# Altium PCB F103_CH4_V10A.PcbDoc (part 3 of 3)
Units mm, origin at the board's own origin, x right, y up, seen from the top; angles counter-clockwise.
Board outline 100.1 x 70.1 mm, 2 copper layers (TOP, BOTTOM), stack 1.6 mm thick; 116 components, 94 nets, 464 pads, 459 vias.
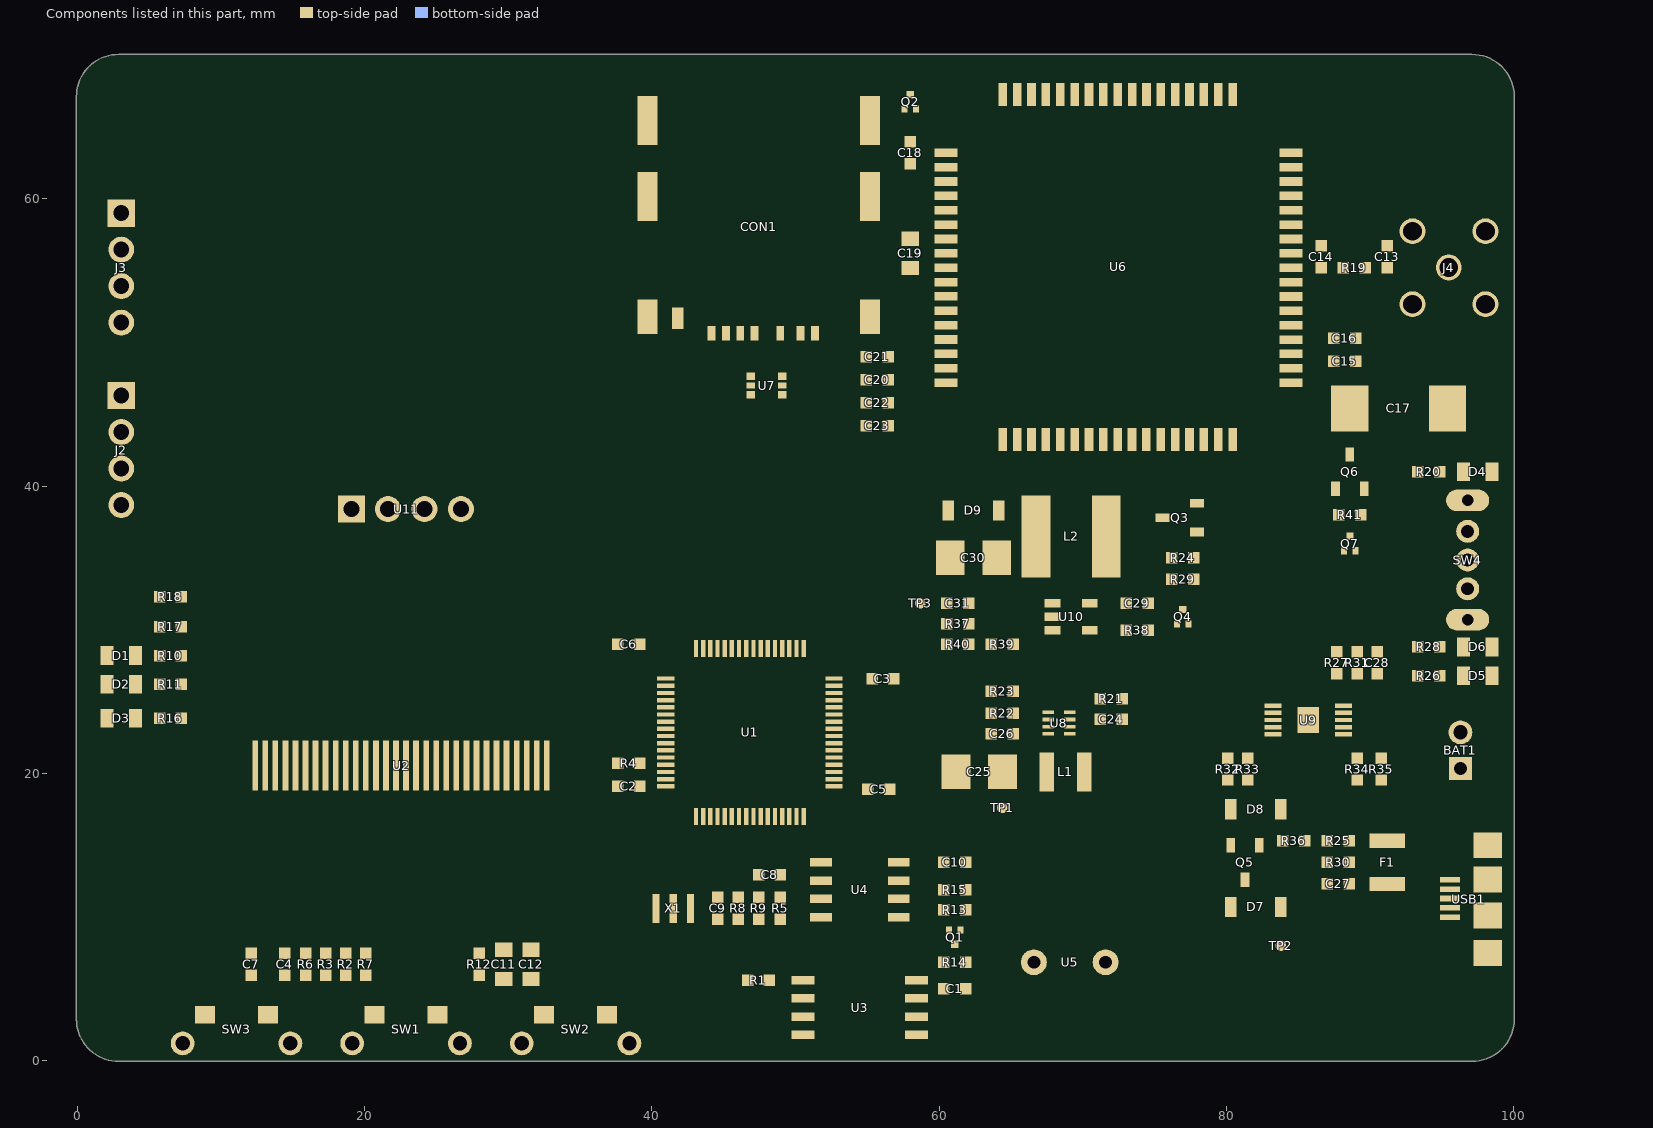
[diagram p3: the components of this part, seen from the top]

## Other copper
TOP:
  pour cut-out: 0,0 0.254,0 0.254,0.254 0,0.254
  pour cut-out: 0,0 0.254,0 0.254,0.254 0,0.254
  pour cut-out: 0,0 0.254,0 0.254,0.254 0,0.254
  pour cut-out: 0,0 0.254,0 0.254,0.254 0,0.254
  pour cut-out: 0,0 0.254,0 0.254,0.254 0,0.254
  pour cut-out: 0,0 0.254,0 0.254,0.254 0,0.254
  pour cut-out: 0,0 0.254,0 0.254,0.254 0,0.254
  pour cut-out: 0,0 0.254,0 0.254,0.254 0,0.254
  pour cut-out: 0,0 0.254,0 0.254,0.254 0,0.254
  pour cut-out: 0,0 0.254,0 0.254,0.254 0,0.254
  pour cut-out: 0,0 0.254,0 0.254,0.254 0,0.254
  pour cut-out: 0,0 0.254,0 0.254,0.254 0,0.254
  pour cut-out: 0,0 0.254,0 0.254,0.254 0,0.254
  pour cut-out: 0,0 0.254,0 0.254,0.254 0,0.254
  pour cut-out: 0,0 0.254,0 0.254,0.254 0,0.254
  pour cut-out: 0,0 0.254,0 0.254,0.254 0,0.254
  pour cut-out: 0,0 0.254,0 0.254,0.254 0,0.254
  pour cut-out: 0,0 0.254,0 0.254,0.254 0,0.254
  pour cut-out: 0,0 0.254,0 0.254,0.254 0,0.254
  pour cut-out: 0,0 0.254,0 0.254,0.254 0,0.254
  pour cut-out: 0,0 0.254,0 0.254,0.254 0,0.254
  pour cut-out: 0,0 0.254,0 0.254,0.254 0,0.254
  pour cut-out: 0,0 0.254,0 0.254,0.254 0,0.254
  pour cut-out: 0,0 0.254,0 0.254,0.254 0,0.254
  pour cut-out: 0,0 0.254,0 0.254,0.254 0,0.254
  pour cut-out: 0,0 0.254,0 0.254,0.254 0,0.254
  pour cut-out: 0,0 0.254,0 0.254,0.254 0,0.254
  pour cut-out: 0,0 0.254,0 0.254,0.254 0,0.254
  pour cut-out: 0,0 0.254,0 0.254,0.254 0,0.254
  pour cut-out: 0,0 0.254,0 0.254,0.254 0,0.254
  pour cut-out: 0,0 0.254,0 0.254,0.254 0,0.254
  pour cut-out: 0,0 0.254,0 0.254,0.254 0,0.254
  pour cut-out: 0,0 0.254,0 0.254,0.254 0,0.254
  pour cut-out: 0,0 0.254,0 0.254,0.254 0,0.254
  pour cut-out: 0,0 0.254,0 0.254,0.254 0,0.254
  pour cut-out: 0,0 0.254,0 0.254,0.254 0,0.254
  pour cut-out: 0,0 0.254,0 0.254,0.254 0,0.254
  pour cut-out: 0,0 0.254,0 0.254,0.254 0,0.254
  pour cut-out: 0,0 0.254,0 0.254,0.254 0,0.254
  pour cut-out: 0,0 0.254,0 0.254,0.254 0,0.254
  pour cut-out: 0,0 0.254,0 0.254,0.254 0,0.254
  pour cut-out: 0,0 0.254,0 0.254,0.254 0,0.254
  pour cut-out: 0,0 0.254,0 0.254,0.254 0,0.254
  pour cut-out: 0,0 0.254,0 0.254,0.254 0,0.254
  pour cut-out: 0,0 0.254,0 0.254,0.254 0,0.254
  pour cut-out: 0,0 0.254,0 0.254,0.254 0,0.254
  pour cut-out: 0,0 0.254,0 0.254,0.254 0,0.254
  pour cut-out: 0,0 0.254,0 0.254,0.254 0,0.254
  pour cut-out: 0,0 0.254,0 0.254,0.254 0,0.254
  pour cut-out: 0,0 0.254,0 0.254,0.254 0,0.254
  pour cut-out: 0,0 0.254,0 0.254,0.254 0,0.254
  pour cut-out: 0,0 0.254,0 0.254,0.254 0,0.254
  pour cut-out: 0,0 0.254,0 0.254,0.254 0,0.254
  pour cut-out: 0,0 0.254,0 0.254,0.254 0,0.254
  pour cut-out: 0,0 0.254,0 0.254,0.254 0,0.254
  pour cut-out: 0,0 0.254,0 0.254,0.254 0,0.254
  pour cut-out: 0,0 0.254,0 0.254,0.254 0,0.254
  pour cut-out: 0,0 0.254,0 0.254,0.254 0,0.254
  pour cut-out: 0,0 0.254,0 0.254,0.254 0,0.254
  pour cut-out: 0,0 0.254,0 0.254,0.254 0,0.254
  pour cut-out: 0,0 0.254,0 0.254,0.254 0,0.254
  pour cut-out: 0,0 0.254,0 0.254,0.254 0,0.254
  pour cut-out: 0,0 0.254,0 0.254,0.254 0,0.254
  pour cut-out: 0,0 0.254,0 0.254,0.254 0,0.254
  pour cut-out: 0,0 0.254,0 0.254,0.254 0,0.254
  pour cut-out: 0,0 0.254,0 0.254,0.254 0,0.254
  pour cut-out: 0,0 0.254,0 0.254,0.254 0,0.254
  pour cut-out: 0,0 0.254,0 0.254,0.254 0,0.254
  pour cut-out: 0,0 0.254,0 0.254,0.254 0,0.254
  pour cut-out: 0,0 0.254,0 0.254,0.254 0,0.254
  pour cut-out: 0,0 0.254,0 0.254,0.254 0,0.254
  pour cut-out: 0,0 0.254,0 0.254,0.254 0,0.254
  pour cut-out: 0,0 0.254,0 0.254,0.254 0,0.254
  pour cut-out: 0,0 0.254,0 0.254,0.254 0,0.254
  pour cut-out: 0,0 0.254,0 0.254,0.254 0,0.254
  pour cut-out: 0,0 0.254,0 0.254,0.254 0,0.254
  pour cut-out: 0,0 0.254,0 0.254,0.254 0,0.254
  pour cut-out: 0,0 0.254,0 0.254,0.254 0,0.254
  pour cut-out: 0,0 0.254,0 0.254,0.254 0,0.254
  pour cut-out: 0,0 0.254,0 0.254,0.254 0,0.254
  pour cut-out: 0,0 0.254,0 0.254,0.254 0,0.254
  pour cut-out: 99.409,57.74 99.362,58.094 99.226,58.425 99.008,58.708 98.725,58.926 98.394,59.062 98.04,59.109 97.686,59.062 97.355,58.926 97.072,58.708 96.854,58.425 96.718,58.094 96.671,57.74 96.718,57.386 96.854,57.055 97.072,56.772 97.355,56.554 97.686,56.418 98.04,56.371 98.394,56.418 98.725,56.554 99.008,56.772 99.226,57.055 99.362,57.386 99.409,57.74
  pour cut-out: 99.409,52.66 99.362,53.014 99.226,53.345 99.008,53.628 98.725,53.846 98.394,53.982 98.04,54.029 97.686,53.982 97.355,53.846 97.072,53.628 96.854,53.345 96.718,53.014 96.671,52.66 96.718,52.306 96.854,51.975 97.072,51.692 97.355,51.474 97.686,51.338 98.04,51.291 98.394,51.338 98.725,51.474 99.008,51.692 99.226,51.975 99.362,52.306 99.409,52.66
  pour cut-out: 94.329,57.74 94.282,58.094 94.146,58.425 93.928,58.708 93.645,58.926 93.314,59.062 92.96,59.109 92.606,59.062 92.275,58.926 91.992,58.708 91.774,58.425 91.638,58.094 91.591,57.74 91.638,57.386 91.774,57.055 91.992,56.772 92.275,56.554 92.606,56.418 92.96,56.371 93.314,56.418 93.645,56.554 93.928,56.772 94.146,57.055 94.282,57.386 94.329,57.74
  pour cut-out: 94.329,52.66 94.282,53.014 94.146,53.345 93.928,53.628 93.645,53.846 93.314,53.982 92.96,54.029 92.606,53.982 92.275,53.846 91.992,53.628 91.774,53.345 91.638,53.014 91.591,52.66 91.638,52.306 91.774,51.975 91.992,51.692 92.275,51.474 92.606,51.338 92.96,51.291 93.314,51.338 93.645,51.474 93.928,51.692 94.146,51.975 94.282,52.306 94.329,52.66
  pour cut-out: 82.255,48.2 82.222,48.535 82.125,48.857 81.966,49.154 81.752,49.414 81.492,49.628 81.195,49.787 80.873,49.884 80.538,49.917 80.203,49.884 79.881,49.787 79.584,49.628 79.324,49.414 79.11,49.154 78.951,48.857 78.854,48.535 78.821,48.2 78.854,47.865 78.951,47.543 79.11,47.246 79.324,46.986 79.584,46.772 79.881,46.613 80.203,46.516 80.538,46.483 80.873,46.516 81.195,46.613 81.492,46.772 81.752,46.986 81.966,47.246 82.125,47.543 82.222,47.865 82.255,48.2
  pour cut-out: 32.912,66.6 32.864,67.09 32.721,67.561 32.489,67.996 32.176,68.376 31.796,68.689 31.361,68.921 30.89,69.064 30.4,69.112 29.91,69.064 29.439,68.921 29.004,68.689 28.624,68.376 28.311,67.996 28.079,67.561 27.936,67.09 27.888,66.6 27.936,66.11 28.079,65.639 28.311,65.204 28.624,64.824 29.004,64.511 29.439,64.279 29.91,64.136 30.4,64.088 30.89,64.136 31.361,64.279 31.796,64.511 32.176,64.824 32.489,65.204 32.721,65.639 32.864,66.11 32.912,66.6
  pour cut-out: 17.912,66.6 17.864,67.09 17.721,67.561 17.489,67.996 17.176,68.376 16.796,68.689 16.361,68.921 15.89,69.064 15.4,69.112 14.91,69.064 14.439,68.921 14.004,68.689 13.624,68.376 13.311,67.996 13.079,67.561 12.936,67.09 12.888,66.6 12.936,66.11 13.079,65.639 13.311,65.204 13.624,64.824 14.004,64.511 14.439,64.279 14.91,64.136 15.4,64.088 15.89,64.136 16.361,64.279 16.796,64.511 17.176,64.824 17.489,65.204 17.721,65.639 17.864,66.11 17.912,66.6
  pour cut-out: 0,0 0.254,0 0.254,0.254 0,0.254
  pour cut-out: 0,0 0.254,0 0.254,0.254 0,0.254
  pour cut-out: 0,0 0.254,0 0.254,0.254 0,0.254
  pour cut-out: 0,0 0.254,0 0.254,0.254 0,0.254
  pour cut-out: 0,0 0.254,0 0.254,0.254 0,0.254
  pour cut-out: 0,0 0.254,0 0.254,0.254 0,0.254
  pour cut-out: 0,0 0.254,0 0.254,0.254 0,0.254
  pour cut-out: 0,0 0.254,0 0.254,0.254 0,0.254
  pour cut-out: 0,0 0.254,0 0.254,0.254 0,0.254
  pour cut-out: 0,0 0.254,0 0.254,0.254 0,0.254
  pour cut-out: 0,0 0.254,0 0.254,0.254 0,0.254
  pour cut-out: 0,0 0.254,0 0.254,0.254 0,0.254
  pour cut-out: 0,0 0.254,0 0.254,0.254 0,0.254
  pour cut-out: 0,0 0.254,0 0.254,0.254 0,0.254
  pour cut-out: 0,0 0.254,0 0.254,0.254 0,0.254
  pour cut-out: 0,0 0.254,0 0.254,0.254 0,0.254
  pour cut-out: 0,0 0.254,0 0.254,0.254 0,0.254
  pour cut-out: 0,0 0.254,0 0.254,0.254 0,0.254
  pour cut-out: 0,0 0.254,0 0.254,0.254 0,0.254
  pour cut-out: 0,0 0.254,0 0.254,0.254 0,0.254
  pour cut-out: 0,0 0.254,0 0.254,0.254 0,0.254
  pour cut-out: 0,0 0.254,0 0.254,0.254 0,0.254
  pour cut-out: 0,0 0.254,0 0.254,0.254 0,0.254
  pour cut-out: 0,0 0.254,0 0.254,0.254 0,0.254
  pour cut-out: 0,0 0.254,0 0.254,0.254 0,0.254
  pour cut-out: 0,0 0.254,0 0.254,0.254 0,0.254
  pour cut-out: 0,0 0.254,0 0.254,0.254 0,0.254
  pour cut-out: 0,0 0.254,0 0.254,0.254 0,0.254
  pour cut-out: 0,0 0.254,0 0.254,0.254 0,0.254
  pour cut-out: 0,0 0.254,0 0.254,0.254 0,0.254
  pour cut-out: 0,0 0.254,0 0.254,0.254 0,0.254
  pour cut-out: 0,0 0.254,0 0.254,0.254 0,0.254
  pour cut-out: 0,0 0.254,0 0.254,0.254 0,0.254
  pour cut-out: 0,0 0.254,0 0.254,0.254 0,0.254
  pour cut-out: 0,0 0.254,0 0.254,0.254 0,0.254
  pour cut-out: 0,0 0.254,0 0.254,0.254 0,0.254
  pour cut-out: 0,0 0.254,0 0.254,0.254 0,0.254
  pour cut-out: 0,0 0.254,0 0.254,0.254 0,0.254
  pour cut-out: 0,0 0.254,0 0.254,0.254 0,0.254
  pour cut-out: 0,0 0.254,0 0.254,0.254 0,0.254
  pour cut-out: 0,0 0.254,0 0.254,0.254 0,0.254
  pour cut-out: 0,0 0.254,0 0.254,0.254 0,0.254
  pour cut-out: 0,0 0.254,0 0.254,0.254 0,0.254
  pour cut-out: 0,0 0.254,0 0.254,0.254 0,0.254
  pour cut-out: 0,0 0.254,0 0.254,0.254 0,0.254
  pour cut-out: 0,0 0.254,0 0.254,0.254 0,0.254
  pour cut-out: 0,0 0.254,0 0.254,0.254 0,0.254
  pour cut-out: 0,0 0.254,0 0.254,0.254 0,0.254
  pour cut-out: 0,0 0.254,0 0.254,0.254 0,0.254
  pour cut-out: 0,0 0.254,0 0.254,0.254 0,0.254
  pour cut-out: 0,0 0.254,0 0.254,0.254 0,0.254
  pour cut-out: 0,0 0.254,0 0.254,0.254 0,0.254
  pour cut-out: 0,0 0.254,0 0.254,0.254 0,0.254
  pour cut-out: 0,0 0.254,0 0.254,0.254 0,0.254
  pour cut-out: 0,0 0.254,0 0.254,0.254 0,0.254
  pour cut-out: 0,0 0.254,0 0.254,0.254 0,0.254
  pour cut-out: 0,0 0.254,0 0.254,0.254 0,0.254
  pour cut-out: 0,0 0.254,0 0.254,0.254 0,0.254
  pour cut-out: 0,0 0.254,0 0.254,0.254 0,0.254
  pour cut-out: 0,0 0.254,0 0.254,0.254 0,0.254
  pour cut-out: 0,0 0.254,0 0.254,0.254 0,0.254
  pour cut-out: 0,0 0.254,0 0.254,0.254 0,0.254
  pour cut-out: 0,0 0.254,0 0.254,0.254 0,0.254
  pour cut-out: 0,0 0.254,0 0.254,0.254 0,0.254
  pour cut-out: 0,0 0.254,0 0.254,0.254 0,0.254
  pour cut-out: 0,0 0.254,0 0.254,0.254 0,0.254
  pour cut-out: 0,0 0.254,0 0.254,0.254 0,0.254
  pour cut-out: 0,0 0.254,0 0.254,0.254 0,0.254
  pour cut-out: 0,0 0.254,0 0.254,0.254 0,0.254
  pour cut-out: 0,0 0.254,0 0.254,0.254 0,0.254
  pour cut-out: 0,0 0.254,0 0.254,0.254 0,0.254
  pour cut-out: 0,0 0.254,0 0.254,0.254 0,0.254
  pour cut-out: 0,0 0.254,0 0.254,0.254 0,0.254
  pour cut-out: 0,0 0.254,0 0.254,0.254 0,0.254
  pour cut-out: 0,0 0.254,0 0.254,0.254 0,0.254
  pour cut-out: 0,0 0.254,0 0.254,0.254 0,0.254
  pour cut-out: 0,0 0.254,0 0.254,0.254 0,0.254
  pour cut-out: 0,0 0.254,0 0.254,0.254 0,0.254
  pour cut-out: 0,0 0.254,0 0.254,0.254 0,0.254
  pour cut-out: 0,0 0.254,0 0.254,0.254 0,0.254
  pour cut-out: 0,0 0.254,0 0.254,0.254 0,0.254
  pour cut-out: 0,0 0.254,0 0.254,0.254 0,0.254
  pour cut-out: 0,0 0.254,0 0.254,0.254 0,0.254
  pour cut-out: 0,0 0.254,0 0.254,0.254 0,0.254
  pour cut-out: 0,0 0.254,0 0.254,0.254 0,0.254
  pour cut-out: 0,0 0.254,0 0.254,0.254 0,0.254
  pour cut-out: 0,0 0.254,0 0.254,0.254 0,0.254
  pour cut-out: 0,0 0.254,0 0.254,0.254 0,0.254
  pour cut-out: 36.462,1.5 36.415,1.734 36.283,1.933 36.084,2.065 35.85,2.112 35.616,2.065 35.417,1.933 35.285,1.734 35.238,1.5 35.285,1.266 35.417,1.067 35.616,0.935 35.85,0.888 36.084,0.935 36.283,1.067 36.415,1.266 36.462,1.5
  pour cut-out: 96.423,13.3 96.398,13.423 96.328,13.528 96.223,13.598 96.1,13.623 95.977,13.598 95.872,13.528 95.802,13.423 95.777,13.3 95.802,13.177 95.872,13.072 95.977,13.002 96.1,12.977 96.223,13.002 96.328,13.072 96.398,13.177 96.423,13.3
  pour cut-out: 0,0 0.254,0 0.254,0.254 0,0.254
  pour cut-out: 0,0 0.254,0 0.254,0.254 0,0.254
  pour cut-out: 0,0 0.254,0 0.254,0.254 0,0.254
  pour cut-out: 0,0 0.254,0 0.254,0.254 0,0.254
  pour cut-out: 12.862,1.5 12.815,1.734 12.683,1.933 12.484,2.065 12.25,2.112 12.016,2.065 11.817,1.933 11.685,1.734 11.638,1.5 11.685,1.266 11.817,1.067 12.016,0.935 12.25,0.888 12.484,0.935 12.683,1.067 12.815,1.266 12.862,1.5
  pour cut-out: 0,0 0.254,0 0.254,0.254 0,0.254
  pour cut-out: 0,0 0.254,0 0.254,0.254 0,0.254
  pour cut-out: 0,0 0.254,0 0.254,0.254 0,0.254
  pour cut-out: 0,0 0.254,0 0.254,0.254 0,0.254
  pour cut-out: 0,0 0.254,0 0.254,0.254 0,0.254
  pour cut-out: 0,0 0.254,0 0.254,0.254 0,0.254
  pour cut-out: 0,0 0.254,0 0.254,0.254 0,0.254
  pour cut-out: 0,0 0.254,0 0.254,0.254 0,0.254
  pour cut-out: 0,0 0.254,0 0.254,0.254 0,0.254
  pour cut-out: 0,0 0.254,0 0.254,0.254 0,0.254
  pour cut-out: 0,0 0.254,0 0.254,0.254 0,0.254
BOTTOM:
  pour cut-out: 24.662,1.5 24.615,1.734 24.483,1.933 24.284,2.065 24.05,2.112 23.816,2.065 23.617,1.933 23.485,1.734 23.438,1.5 23.485,1.266 23.617,1.067 23.816,0.935 24.05,0.888 24.284,0.935 24.483,1.067 24.615,1.266 24.662,1.5
  pour cut-out: 22.362,1.5 22.315,1.734 22.183,1.933 21.984,2.065 21.75,2.112 21.516,2.065 21.317,1.933 21.185,1.734 21.138,1.5 21.185,1.266 21.317,1.067 21.516,0.935 21.75,0.888 21.984,0.935 22.183,1.067 22.315,1.266 22.362,1.5
  pour cut-out: 99.409,57.74 99.362,58.094 99.226,58.425 99.008,58.708 98.725,58.926 98.394,59.062 98.04,59.109 97.686,59.062 97.355,58.926 97.072,58.708 96.854,58.425 96.718,58.094 96.671,57.74 96.718,57.386 96.854,57.055 97.072,56.772 97.355,56.554 97.686,56.418 98.04,56.371 98.394,56.418 98.725,56.554 99.008,56.772 99.226,57.055 99.362,57.386 99.409,57.74
  pour cut-out: 99.409,52.66 99.362,53.014 99.226,53.345 99.008,53.628 98.725,53.846 98.394,53.982 98.04,54.029 97.686,53.982 97.355,53.846 97.072,53.628 96.854,53.345 96.718,53.014 96.671,52.66 96.718,52.306 96.854,51.975 97.072,51.692 97.355,51.474 97.686,51.338 98.04,51.291 98.394,51.338 98.725,51.474 99.008,51.692 99.226,51.975 99.362,52.306 99.409,52.66
  pour cut-out: 96.904,55.216 96.856,55.584 96.714,55.926 96.488,56.22 96.194,56.446 95.852,56.588 95.484,56.636 95.116,56.588 94.774,56.446 94.48,56.22 94.254,55.926 94.112,55.584 94.064,55.216 94.112,54.848 94.254,54.506 94.48,54.212 94.774,53.986 95.116,53.844 95.484,53.796 95.852,53.844 96.194,53.986 96.488,54.212 96.714,54.506 96.856,54.848 96.904,55.216
  pour cut-out: 94.329,57.74 94.282,58.094 94.146,58.425 93.928,58.708 93.645,58.926 93.314,59.062 92.96,59.109 92.606,59.062 92.275,58.926 91.992,58.708 91.774,58.425 91.638,58.094 91.591,57.74 91.638,57.386 91.774,57.055 91.992,56.772 92.275,56.554 92.606,56.418 92.96,56.371 93.314,56.418 93.645,56.554 93.928,56.772 94.146,57.055 94.282,57.386 94.329,57.74
  pour cut-out: 94.329,52.66 94.282,53.014 94.146,53.345 93.928,53.628 93.645,53.846 93.314,53.982 92.96,54.029 92.606,53.982 92.275,53.846 91.992,53.628 91.774,53.345 91.638,53.014 91.591,52.66 91.638,52.306 91.774,51.975 91.992,51.692 92.275,51.474 92.606,51.338 92.96,51.291 93.314,51.338 93.645,51.474 93.928,51.692 94.146,51.975 94.282,52.306 94.329,52.66
  pour cut-out: 73.02,6.85 72.972,7.218 72.83,7.56 72.604,7.854 72.31,8.08 71.968,8.222 71.6,8.27 71.232,8.222 70.89,8.08 70.596,7.854 70.37,7.56 70.228,7.218 70.18,6.85 70.228,6.482 70.37,6.14 70.596,5.846 70.89,5.62 71.232,5.478 71.6,5.43 71.968,5.478 72.31,5.62 72.604,5.846 72.83,6.14 72.972,6.482 73.02,6.85
  pour cut-out: 68.02,6.85 67.972,7.218 67.83,7.56 67.604,7.854 67.31,8.08 66.968,8.222 66.6,8.27 66.232,8.222 65.89,8.08 65.596,7.854 65.37,7.56 65.228,7.218 65.18,6.85 65.228,6.482 65.37,6.14 65.596,5.846 65.89,5.62 66.232,5.478 66.6,5.43 66.968,5.478 67.31,5.62 67.604,5.846 67.83,6.14 67.972,6.482 68.02,6.85
  pour cut-out: 96.423,13.3 96.398,13.423 96.328,13.528 96.223,13.598 96.1,13.623 95.977,13.598 95.872,13.528 95.802,13.423 95.777,13.3 95.802,13.177 95.872,13.072 95.977,13.002 96.1,12.977 96.223,13.002 96.328,13.072 96.398,13.177 96.423,13.3
  pour cut-out: 96.423,9.3 96.398,9.423 96.328,9.528 96.223,9.598 96.1,9.623 95.977,9.598 95.872,9.528 95.802,9.423 95.777,9.3 95.802,9.177 95.872,9.072 95.977,9.002 96.1,8.977 96.223,9.002 96.328,9.072 96.398,9.177 96.423,9.3
  pour cut-out: 82.255,48.2 82.222,48.535 82.125,48.857 81.966,49.154 81.752,49.414 81.492,49.628 81.195,49.787 80.873,49.884 80.538,49.917 80.203,49.884 79.881,49.787 79.584,49.628 79.324,49.414 79.11,49.154 78.951,48.857 78.854,48.535 78.821,48.2 78.854,47.865 78.951,47.543 79.11,47.246 79.324,46.986 79.584,46.772 79.881,46.613 80.203,46.516 80.538,46.483 80.873,46.516 81.195,46.613 81.492,46.772 81.752,46.986 81.966,47.246 82.125,47.543 82.222,47.865 82.255,48.2
  pour cut-out: 36.462,1.5 36.415,1.734 36.283,1.933 36.084,2.065 35.85,2.112 35.616,2.065 35.417,1.933 35.285,1.734 35.238,1.5 35.285,1.266 35.417,1.067 35.616,0.935 35.85,0.888 36.084,0.935 36.283,1.067 36.415,1.266 36.462,1.5
  pour cut-out: 34.162,1.5 34.115,1.734 33.983,1.933 33.784,2.065 33.55,2.112 33.316,2.065 33.117,1.933 32.985,1.734 32.938,1.5 32.985,1.266 33.117,1.067 33.316,0.935 33.55,0.888 33.784,0.935 33.983,1.067 34.115,1.266 34.162,1.5
  pour cut-out: 32.912,66.6 32.864,67.09 32.721,67.561 32.489,67.996 32.176,68.376 31.796,68.689 31.361,68.921 30.89,69.064 30.4,69.112 29.91,69.064 29.439,68.921 29.004,68.689 28.624,68.376 28.311,67.996 28.079,67.561 27.936,67.09 27.888,66.6 27.936,66.11 28.079,65.639 28.311,65.204 28.624,64.824 29.004,64.511 29.439,64.279 29.91,64.136 30.4,64.088 30.89,64.136 31.361,64.279 31.796,64.511 32.176,64.824 32.489,65.204 32.721,65.639 32.864,66.11 32.912,66.6
  pour cut-out: 17.912,66.6 17.864,67.09 17.721,67.561 17.489,67.996 17.176,68.376 16.796,68.689 16.361,68.921 15.89,69.064 15.4,69.112 14.91,69.064 14.439,68.921 14.004,68.689 13.624,68.376 13.311,67.996 13.079,67.561 12.936,67.09 12.888,66.6 12.936,66.11 13.079,65.639 13.311,65.204 13.624,64.824 14.004,64.511 14.439,64.279 14.91,64.136 15.4,64.088 15.89,64.136 16.361,64.279 16.796,64.511 17.176,64.824 17.489,65.204 17.721,65.639 17.864,66.11 17.912,66.6
  pour cut-out: 12.862,1.5 12.815,1.734 12.683,1.933 12.484,2.065 12.25,2.112 12.016,2.065 11.817,1.933 11.685,1.734 11.638,1.5 11.685,1.266 11.817,1.067 12.016,0.935 12.25,0.888 12.484,0.935 12.683,1.067 12.815,1.266 12.862,1.5
  pour cut-out: 10.562,1.5 10.515,1.734 10.383,1.933 10.184,2.065 9.95,2.112 9.716,2.065 9.517,1.933 9.385,1.734 9.338,1.5 9.385,1.266 9.517,1.067 9.716,0.935 9.95,0.888 10.184,0.935 10.383,1.067 10.515,1.266 10.562,1.5
  pour cut-out: 0,0 0.254,0 0.254,0.254 0,0.254
  pour cut-out: 0,0 0.254,0 0.254,0.254 0,0.254
  pour cut-out: 0,0 0.254,0 0.254,0.254 0,0.254
  pour cut-out: 0,0 0.254,0 0.254,0.254 0,0.254
  pour cut-out: 0,0 0.254,0 0.254,0.254 0,0.254
  pour cut-out: 0,0 0.254,0 0.254,0.254 0,0.254
  pour cut-out: 0,0 0.254,0 0.254,0.254 0,0.254
  pour cut-out: 0,0 0.254,0 0.254,0.254 0,0.254
  pour cut-out: 0,0 0.254,0 0.254,0.254 0,0.254
  pour cut-out: 0,0 0.254,0 0.254,0.254 0,0.254
  pour cut-out: 0,0 0.254,0 0.254,0.254 0,0.254
  pour cut-out: 0,0 0.254,0 0.254,0.254 0,0.254
  pour cut-out: 0,0 0.254,0 0.254,0.254 0,0.254
  pour cut-out: 0,0 0.254,0 0.254,0.254 0,0.254
  pour cut-out: 0,0 0.254,0 0.254,0.254 0,0.254
  pour cut-out: 0,0 0.254,0 0.254,0.254 0,0.254
  pour cut-out: 0,0 0.254,0 0.254,0.254 0,0.254
  pour cut-out: 0,0 0.254,0 0.254,0.254 0,0.254
  pour cut-out: 0,0 0.254,0 0.254,0.254 0,0.254
  pour cut-out: 0,0 0.254,0 0.254,0.254 0,0.254
  pour cut-out: 0,0 0.254,0 0.254,0.254 0,0.254
  pour cut-out: 0,0 0.254,0 0.254,0.254 0,0.254
  pour cut-out: 0,0 0.254,0 0.254,0.254 0,0.254
  pour cut-out: 0,0 0.254,0 0.254,0.254 0,0.254
  pour cut-out: 0,0 0.254,0 0.254,0.254 0,0.254
  pour cut-out: 0,0 0.254,0 0.254,0.254 0,0.254
  pour cut-out: 0,0 0.254,0 0.254,0.254 0,0.254
  pour cut-out: 0,0 0.254,0 0.254,0.254 0,0.254
  pour cut-out: 0,0 0.254,0 0.254,0.254 0,0.254
  pour cut-out: 0,0 0.254,0 0.254,0.254 0,0.254
  pour cut-out: 0,0 0.254,0 0.254,0.254 0,0.254
  pour cut-out: 0,0 0.254,0 0.254,0.254 0,0.254
  pour cut-out: 0,0 0.254,0 0.254,0.254 0,0.254
  pour cut-out: 0,0 0.254,0 0.254,0.254 0,0.254
  pour cut-out: 0,0 0.254,0 0.254,0.254 0,0.254
  pour cut-out: 0,0 0.254,0 0.254,0.254 0,0.254
  pour cut-out: 0,0 0.254,0 0.254,0.254 0,0.254
  pour cut-out: 0,0 0.254,0 0.254,0.254 0,0.254
  pour cut-out: 0,0 0.254,0 0.254,0.254 0,0.254
  pour cut-out: 0,0 0.254,0 0.254,0.254 0,0.254
  pour cut-out: 0,0 0.254,0 0.254,0.254 0,0.254
  pour cut-out: 0,0 0.254,0 0.254,0.254 0,0.254
  pour cut-out: 0,0 0.254,0 0.254,0.254 0,0.254
  pour cut-out: 0,0 0.254,0 0.254,0.254 0,0.254
  pour cut-out: 0,0 0.254,0 0.254,0.254 0,0.254
  pour cut-out: 0,0 0.254,0 0.254,0.254 0,0.254
  pour cut-out: 0,0 0.254,0 0.254,0.254 0,0.254
  pour cut-out: 0,0 0.254,0 0.254,0.254 0,0.254
  pour cut-out: 0,0 0.254,0 0.254,0.254 0,0.254
  pour cut-out: 0,0 0.254,0 0.254,0.254 0,0.254
  pour cut-out: 0,0 0.254,0 0.254,0.254 0,0.254
  pour cut-out: 0,0 0.254,0 0.254,0.254 0,0.254
  pour cut-out: 0,0 0.254,0 0.254,0.254 0,0.254
  pour cut-out: 0,0 0.254,0 0.254,0.254 0,0.254
  pour cut-out: 0,0 0.254,0 0.254,0.254 0,0.254
  pour cut-out: 0,0 0.254,0 0.254,0.254 0,0.254
  pour cut-out: 0,0 0.254,0 0.254,0.254 0,0.254
  pour cut-out: 0,0 0.254,0 0.254,0.254 0,0.254
  pour cut-out: 0,0 0.254,0 0.254,0.254 0,0.254
  pour cut-out: 0,0 0.254,0 0.254,0.254 0,0.254
  pour cut-out: 0,0 0.254,0 0.254,0.254 0,0.254
  pour cut-out: 0,0 0.254,0 0.254,0.254 0,0.254
  pour cut-out: 0,0 0.254,0 0.254,0.254 0,0.254
  pour cut-out: 0,0 0.254,0 0.254,0.254 0,0.254
  pour cut-out: 0,0 0.254,0 0.254,0.254 0,0.254
  pour cut-out: 0,0 0.254,0 0.254,0.254 0,0.254
  pour cut-out: 0,0 0.254,0 0.254,0.254 0,0.254
  pour cut-out: 0,0 0.254,0 0.254,0.254 0,0.254
  pour cut-out: 0,0 0.254,0 0.254,0.254 0,0.254
  pour cut-out: 0,0 0.254,0 0.254,0.254 0,0.254
  pour cut-out: 0,0 0.254,0 0.254,0.254 0,0.254
  pour cut-out: 0,0 0.254,0 0.254,0.254 0,0.254
  pour cut-out: 0,0 0.254,0 0.254,0.254 0,0.254
  pour cut-out: 0,0 0.254,0 0.254,0.254 0,0.254
  pour cut-out: 0,0 0.254,0 0.254,0.254 0,0.254
  pour cut-out: 0,0 0.254,0 0.254,0.254 0,0.254
  pour cut-out: 0,0 0.254,0 0.254,0.254 0,0.254
  pour cut-out: 0,0 0.254,0 0.254,0.254 0,0.254
  pour cut-out: 0,0 0.254,0 0.254,0.254 0,0.254
  pour cut-out: 0,0 0.254,0 0.254,0.254 0,0.254
  pour cut-out: 0,0 0.254,0 0.254,0.254 0,0.254
  pour cut-out: 0,0 0.254,0 0.254,0.254 0,0.254
  pour cut-out: 0,0 0.254,0 0.254,0.254 0,0.254
  pour cut-out: 0,0 0.254,0 0.254,0.254 0,0.254
  pour cut-out: 0,0 0.254,0 0.254,0.254 0,0.254
  pour cut-out: 0,0 0.254,0 0.254,0.254 0,0.254
  pour cut-out: 0,0 0.254,0 0.254,0.254 0,0.254
  pour cut-out: 0,0 0.254,0 0.254,0.254 0,0.254
  pour cut-out: 0,0 0.254,0 0.254,0.254 0,0.254
  pour cut-out: 0,0 0.254,0 0.254,0.254 0,0.254
  pour cut-out: 0,0 0.254,0 0.254,0.254 0,0.254
  pour cut-out: 0,0 0.254,0 0.254,0.254 0,0.254
  pour cut-out: 0,0 0.254,0 0.254,0.254 0,0.254
  pour cut-out: 0,0 0.254,0 0.254,0.254 0,0.254
  pour cut-out: 0,0 0.254,0 0.254,0.254 0,0.254
  pour cut-out: 0,0 0.254,0 0.254,0.254 0,0.254
  pour cut-out: 0,0 0.254,0 0.254,0.254 0,0.254
  pour cut-out: 0,0 0.254,0 0.254,0.254 0,0.254
  pour cut-out: 0,0 0.254,0 0.254,0.254 0,0.254
  pour cut-out: 0,0 0.254,0 0.254,0.254 0,0.254
  pour cut-out: 0,0 0.254,0 0.254,0.254 0,0.254
  pour cut-out: 0,0 0.254,0 0.254,0.254 0,0.254
  pour cut-out: 0,0 0.254,0 0.254,0.254 0,0.254
  pour cut-out: 0,0 0.254,0 0.254,0.254 0,0.254
  pour cut-out: 0,0 0.254,0 0.254,0.254 0,0.254
  pour cut-out: 0,0 0.254,0 0.254,0.254 0,0.254
  pour cut-out: 0,0 0.254,0 0.254,0.254 0,0.254
  pour cut-out: 0,0 0.254,0 0.254,0.254 0,0.254
  pour cut-out: 0,0 0.254,0 0.254,0.254 0,0.254
  pour cut-out: 0,0 0.254,0 0.254,0.254 0,0.254
  pour cut-out: 0,0 0.254,0 0.254,0.254 0,0.254
  pour cut-out: 0,0 0.254,0 0.254,0.254 0,0.254
  pour cut-out: 0,0 0.254,0 0.254,0.254 0,0.254
  pour cut-out: 0,0 0.254,0 0.254,0.254 0,0.254
  pour cut-out: 0,0 0.254,0 0.254,0.254 0,0.254
  pour cut-out: 0,0 0.254,0 0.254,0.254 0,0.254
  pour cut-out: 0,0 0.254,0 0.254,0.254 0,0.254
  pour cut-out: 0,0 0.254,0 0.254,0.254 0,0.254
  pour cut-out: 0,0 0.254,0 0.254,0.254 0,0.254
  pour cut-out: 0,0 0.254,0 0.254,0.254 0,0.254
  pour cut-out: 0,0 0.254,0 0.254,0.254 0,0.254
  pour cut-out: 0,0 0.254,0 0.254,0.254 0,0.254
  pour cut-out: 0,0 0.254,0 0.254,0.254 0,0.254
  pour cut-out: 0,0 0.254,0 0.254,0.254 0,0.254
  pour cut-out: 0,0 0.254,0 0.254,0.254 0,0.254
  pour cut-out: 0,0 0.254,0 0.254,0.254 0,0.254
  pour cut-out: 0,0 0.254,0 0.254,0.254 0,0.254
  pour cut-out: 0,0 0.254,0 0.254,0.254 0,0.254
  pour cut-out: 0,0 0.254,0 0.254,0.254 0,0.254
  pour cut-out: 0,0 0.254,0 0.254,0.254 0,0.254
  pour cut-out: 0,0 0.254,0 0.254,0.254 0,0.254
  pour cut-out: 0,0 0.254,0 0.254,0.254 0,0.254
  pour cut-out: 0,0 0.254,0 0.254,0.254 0,0.254
  pour cut-out: 0,0 0.254,0 0.254,0.254 0,0.254
  pour cut-out: 0,0 0.254,0 0.254,0.254 0,0.254
  pour cut-out: 0,0 0.254,0 0.254,0.254 0,0.254
  pour cut-out: 0,0 0.254,0 0.254,0.254 0,0.254
  pour cut-out: 0,0 0.254,0 0.254,0.254 0,0.254
  pour cut-out: 0,0 0.254,0 0.254,0.254 0,0.254
  pour cut-out: 0,0 0.254,0 0.254,0.254 0,0.254
  pour cut-out: 0,0 0.254,0 0.254,0.254 0,0.254
  pour cut-out: 0,0 0.254,0 0.254,0.254 0,0.254
  pour cut-out: 0,0 0.254,0 0.254,0.254 0,0.254
  pour cut-out: 0,0 0.254,0 0.254,0.254 0,0.254
  pour cut-out: 0,0 0.254,0 0.254,0.254 0,0.254
  pour cut-out: 0,0 0.254,0 0.254,0.254 0,0.254
  pour cut-out: 0,0 0.254,0 0.254,0.254 0,0.254
  pour cut-out: 0,0 0.254,0 0.254,0.254 0,0.254
  pour cut-out: 0,0 0.254,0 0.254,0.254 0,0.254
  pour cut-out: 0,0 0.254,0 0.254,0.254 0,0.254
  pour cut-out: 0,0 0.254,0 0.254,0.254 0,0.254
  pour cut-out: 0,0 0.254,0 0.254,0.254 0,0.254
  pour cut-out: 0,0 0.254,0 0.254,0.254 0,0.254
  pour cut-out: 0,0 0.254,0 0.254,0.254 0,0.254
  pour cut-out: 0,0 0.254,0 0.254,0.254 0,0.254
  pour cut-out: 0,0 0.254,0 0.254,0.254 0,0.254
  pour cut-out: 0,0 0.254,0 0.254,0.254 0,0.254
  pour cut-out: 0,0 0.254,0 0.254,0.254 0,0.254
  pour cut-out: 0,0 0.254,0 0.254,0.254 0,0.254

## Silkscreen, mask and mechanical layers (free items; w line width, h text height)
CUTOUT:
  lines w0.1: 0,2.9 ccw(c2.9,2.9) 2.9,0 97.1,0 ccw(c97.1,2.9) 100,2.9 100,67.1 ccw(c97.1,67.1) 97.1,70 2.9,70 ccw(c2.9,67.1) 0,67.1 0,2.9
DIMENSION:
  circle w0.025: c106.004,72.5 r0.953
  lines w0.025: -23.5,0 -2.5,0 ; -23.5,70 6.6,70 ; -21,32.843 -21,0 ; -21,37.757 -21,70 ; -16.9,0 -2.5,0 ; -16.9,67.1 0.4,67.1 ; -14.4,29.743 -14.4,0 ; -14.4,34.657 -14.4,67.1 ; -13.6,0 -2.5,0 ; -13.6,2.9 0.4,2.9 ; -11.1,-8 -11.1,0 ; -11.1,7.843 -11.1,2.9 ; -8,-4.4 0,-4.4 ; 0,-15.2 0,-2.5 ; 0,-10.9 0,-2.5 ; 0,-6.9 0,-2.5 ; 2.9,-6.9 2.9,0.4 ; 7.779,-4.4 2.9,-4.4 ; 43.826,-8.4 0,-8.4 ; 46.379,-12.7 0,-12.7 ; 53.974,-8.4 97.1,-8.4 ; 54.621,-12.7 100,-12.7 ; 97.1,-10.9 97.1,0.4 ; 100,-15.2 100,0.6 ; 103.623,72.5 101.6,72.5 98.124,68.329 ; 105.052,71.071 106.957,73.929 ; -21,0 -20.375,4 -21.625,4 -21,0 ; -21,70 -21.625,66 -20.375,66 -21,70 ; -14.4,0 -13.775,4 -15.025,4 -14.4,0 ; -14.4,67.1 -15.025,63.1 -13.775,63.1 -14.4,67.1 ; -11.1,0 -11.725,-4 -10.475,-4 -11.1,0 ; -11.1,2.9 -10.475,6.9 -11.725,6.9 -11.1,2.9 ; 0,-12.7 4,-13.325 4,-12.075 0,-12.7 ; 0,-8.4 4,-9.025 4,-7.775 0,-8.4 ; 0,-4.4 -4,-3.775 -4,-5.025 0,-4.4 ; 2.9,-4.4 6.9,-5.025 6.9,-3.775 2.9,-4.4 ; 97.1,-8.4 93.1,-7.775 93.1,-9.025 97.1,-8.4 ; 98.124,68.329 101.165,71.002 100.205,71.802 98.124,68.329 ; 100,-12.7 96,-12.075 96,-13.325 100,-12.7
  text "3.2" at 107.44,71.547 h1.91
  text "70" at -22.664,34.348 h1.91
  text "67.1" at -17.969,31.247 h1.91
  text "2.9" at -13.716,9.347 h1.91
  text "2.9" at 9.284,-5.352 h1.91
  text "97.1" at 45.331,-9.353 h1.91
  text "100" at 47.884,-13.652 h1.91
PHOTOPLOT_OUTLINE:
  lines w0.025: -115.9,-86.525 -115.9,535.14 791.515,535.14 791.515,-86.525 -115.9,-86.525
NCLEGEND-1-2:
  lines w0.025: 119,6.15 244.984,6.15 ; 119,12.5 244.984,12.5 ; 119,18.85 244.984,18.85 ; 119,25.2 244.984,25.2 ; 119,31.55 244.984,31.55 ; 119,37.9 244.984,37.9 ; 119,44.25 244.984,44.25 ; 119,50.6 244.984,50.6 ; 130.265,34.725 130.57,34.725 ; 130.417,34.573 130.417,34.877 ; 141.835,-0.2 141.835,44.25 ; 193.016,-0.2 193.016,44.25 ; 225.299,-0.2 225.299,44.25 ; 119,-0.2 119,57.1 244.984,57.1 244.984,-0.2 119,-0.2 ; 129.01,9.325 129.422,8.33 130.417,7.918 131.412,8.33 131.824,9.325 131.412,10.32 130.417,10.732 129.422,10.32 129.01,9.325 ; 129.617,2.175 ccw(c129.617,2.975) 129.617,3.775 131.217,3.775 ccw(c131.217,2.975) 131.217,2.175 129.617,2.175 ; 129.867,15.4 130.417,15.125 130.967,15.4 130.967,15.95 130.417,16.225 129.867,15.95 129.867,15.4 ; 129.917,22.025 130.167,21.525 130.667,21.525 130.917,22.025 130.667,22.525 130.167,22.525 129.917,22.025 ; 129.967,27.925 130.867,27.925 130.867,28.825 129.967,28.825 129.967,27.925
  text "DRILL CHART: TOP to BOTTOM" at 148.972,52.338 h3.17
  text "ALL UNITS ARE IN MILLIMETERS" at 146.432,45.838 h3.17
  text "FIGURE" at 122.797,39.488 h3.17
  text "FINISHED_SIZE" at 150.915,39.488 h3.17
  text "PLATED" at 201.537,39.488 h3.17
  text "QTY" at 231.332,39.488 h3.17
  text "0.3048" at 159.805,33.138 h3.17
  text "PLATED" at 201.537,33.138 h3.17
  text "459" at 231.332,33.138 h3.17
  text "0.9" at 163.615,26.788 h3.17
  text "PLATED" at 201.537,26.788 h3.17
  text "6" at 233.872,26.788 h3.17
  text "1.0" at 163.615,20.438 h3.17
  text "PLATED" at 201.537,20.438 h3.17
  text "7" at 233.872,20.438 h3.17
  text "1.1" at 163.615,14.088 h3.17
  text "PLATED" at 201.537,14.088 h3.17
  text "12" at 232.602,14.088 h3.17
  text "1.3" at 163.615,7.738 h3.17
  text "PLATED" at 201.537,7.738 h3.17
  text "5" at 233.872,7.738 h3.17
  text "2.4x0.8" at 158.535,1.388 h3.17
  text "PLATED" at 201.537,1.388 h3.17
  text "2" at 233.872,1.388 h3.17
  text "TOTAL HOLES:" at 191.644,-4.962 h3.17
  text "491" at 231.332,-4.962 h3.17
DETAILS:
  drawing of 2649 lines, arcs and shapes, not listed
  text "V10A" at 581.457,472.275 h2.54
  text "XXXLZJXXX" at 725.602,472.148 h2.54
  text "19-02-15" at 699.821,472.021 h2.54
  text "DETAIL A" at -27.254,437.919 h3.17
  text "1. THIS DRAWING SPECIFIES THE REQUIREMENTS FOR A" at 409.753,433.982 h2.39
  text "PRINTED WIRING BOARD IN ACCORDANCE" at 518.973,433.982 h2.39
  text "LAYER STACKUP" at -33.604,430.299 h3.17
  text "WITH SPECIFICATION IPC-A-600 CLASS 2 (LATEST REVISION)." at 412.293,428.902 h2.39
  text "SCALE: NONE" at -19.888,423.949 h0.64
  text "2. THE PWB MUST BE LEAD FREE ASSEMBLY PROCESS COMPATIBLE AND MUST BE ABLE TO HANDLE" at 409.753,418.742 h2.39
  text "A MINIMUM OF 5 CYCLES AT 260 DEGREES CELSIUS FOR 10 SECONDS." at 412.293,413.662 h2.39
  text "DETAIL B" at 248.836,407.686 h3.17
  text "JLC:  1.6mm THK +/- 10%" at -52.654,405.534 h3.17
  text "FINISHED Cu WEIGHT" at 83.998,404.01 h3.17
  text "3. BASE MATERIAL - LAMINATE AND PREPREG SHALL MEET IPC-4101B-26, 83 or 98" at 409.753,403.502 h2.39
  text "IMPEDANCE REQUIREMENTS" at 231.463,402.302 h3.17
  text "IMPEDANCE TOLERANCE IS 10%" at 226.383,397.222 h3.17
  text "Tg - MUST BE GREATER THAN OR EQUAL TO 150 DEGREES CELSIUS." at 409.753,393.342 h2.39
  text "LAYER 1  TOP SIDE          1oz+plating" at 31.166,389.024 h3.17
  text "Td - MUST BE GREATER THAN OR EQUAL TO 330 DEGREES CELSIUS." at 409.753,388.262 h2.39
  text "Single Ended" at 215.912,387.849 h0.51
  text "Differential" at 267.054,387.756 h0.51
  text "Differential" at 329.799,387.756 h0.51
  text "Impedance" at 295.033,382.744 h1.6
  text "Impedance" at 357.777,382.744 h1.6
  text "Impedance" at 233.311,382.617 h1.6
  text "Layers" at 191.68,382.566 h0.51
  text "Trace Spacing" at 271.69,382.566 h1.6
  text "Trace Spacing" at 334.435,382.566 h1.6
  text "Trace Width" at 212.102,382.363 h1.6
  text "Trace Width" at 251.726,382.363 h1.6
  text "Trace Width" at 314.47,382.363 h1.6
  text "(Mils)" at 213.27,380.026 h1.6
  text "(Ohms)" at 233.59,380.026 h1.6
  text "(Mils)" at 252.64,380.026 h1.6
  text "\"Airgap\"" at 271.69,380.026 h1.6
  text "(Ohms)" at 295.82,380.026 h1.6
  text "(Mils)" at 315.385,380.026 h1.6
  text "\"Airgap\"" at 334.435,380.026 h1.6
  text "(Ohms)" at 358.565,380.026 h1.6
  text "A_TARGET:1.53 mm" at -18.745,378.99 h1.6
  text "4. COPPER FOIL WEIGHT - SEE STACKUP DETAIL 'A'" at 409.753,378.102 h2.39
  text "(Mils)" at 276.465,377.105 h1.6
  text "(Mils)" at 339.21,377.105 h1.6
  text "L1" at 191.655,372.33 h0.9
  text "4.2" at 257.187,372.076 h0.9
  text "4.70" at 319.931,372.076 h0.9
  text "5.00" at 217.69,371.949 h0.9
  text "100" at 299.63,371.771 h0.9
  text "90" at 362.375,371.771 h0.9
  text "6.00" at 274.967,371.695 h0.9
  text "5.00" at 337.711,371.695 h0.9
  text "50" at 240.55,371.568 h0.9
  text "5. CHARACTERISTIC IMPEDANCE - SEE DETAIL 'B'" at 409.753,367.942 h2.39
  text "L4" at 191.655,367.25 h0.9
  text "4.70" at 319.931,366.996 h0.9
  text "5.00" at 217.69,366.869 h0.9
  text "90" at 362.375,366.691 h0.9
  text "5.00" at 337.711,366.615 h0.9
  text "50" at 240.55,366.488 h0.9
  text "LAYER 2  BOTTOM SIDE       1oz+plating" at 31.166,366.164 h3.17
  text "6. MINIMUM CONDUCTIVE WIDTH/SPACING TO BE .00X\"/.00X\"" at 409.753,359.052 h2.39
  text "7. PLATING FINISH - BOTH SIDES ENIG (ELECTROLESS NICKEL IMMERSION GOLD):" at 409.753,348.892 h2.39
  text ".05080-.232 MICRON (2-8 MICROINCH) OF GOLD OVER" at 456.387,343.761 h2.39
  text "2.540-6.350 MICRON (100-250 MICROINCH) OF NICKEL." at 449.479,338.757 h2.39
  text "If the angle of PCB board outline is right angle,please use this kind of break out area" at 581.33,336.7 h0.79
  text "If not use it,please delete it before you gerber out" at 581.33,331.62 h0.79
  text "8. ALL THROUGH HOLE VIAS MAY BE PLATED SHUT." at 409.753,328.572 h2.39
  text "9. SOLDERMASK - GREEN COLOR (TAIYO OR EQUIVALENT), BOTH SIDES." at 410.49,319.022 h2.39
  text "MODIFICATION OF SOLDERMASK IS NOT ALLOWED WITHOUT WRITTEN PERMISSION FROM FREESCALE." at 410.515,313.332 h2.39
  text "If the angle of PCB board outline is circular,please use this kind of break out area" at 580.06,308.76 h0.79
  text "If not use it,please delete it before you gerber out" at 580.06,304.95 h0.79
  text "10. SILKSCREEN - WHITE EPOXY INK, BOTH SIDES.  NO SILK ON PADS." at 410.49,303.782 h2.39
  text "11. ELECTRICAL TEST - 100% IPCD356." at 410.49,293.622 h2.39
  text "12. PRINTED WIRING BOARD IS TO BE INDIVIDUALLY BAGGED." at 410.49,283.462 h2.39
  text "If not use it,please delete it before you gerber out" at 581.33,275.74 h0.79
  text "13. DRC'S MUST BE RUN ON THE GERBER BEFORE BUILDING BOARDS," at 410.49,273.302 h2.39
  text "UNLESS PRIOR APPROVAL IS GIVEN IN WRITING BY FREESCALE." at 410.49,268.222 h2.39
  text "AS usual,please use the 0.8MM stamp Via" at 581.33,268.12 h0.79
  text "14. ADD TEARDROPS TO ALL SIGNAL LAYERS." at 410.49,258.062 h2.39
  text "15. SOLDER SAMPLES TO BE PROVIDED." at 410.49,247.902 h2.39
  text "16. BASIC GRID INCREMENT AT 1:1 IS .0001." at 410.49,237.742 h2.39
  text "17. SUPPLIER MARKINGS - ON SOLDER SIDE ONLY, WHERE SHOWN." at 410.49,225.042 h2.39
  text "- MUST BE UL RECOGNIZED AND MUST HAVE AN ID THAT CONFORMS TO UL94V-0" at 409.753,219.352 h2.39
  text "If not use it,please delete it before you gerber out" at 605.46,213.51 h0.79
  text "18. THE PWB WILL BE MARKED AS LEAD FREE BY USE OF AN INK STAMP Pb" at 413.03,207.897 h2.39
  text "19. THE PWB WILL BE MARKED AS LEAD FREE PROCESS COMPATIBLE BY USE OF AN INK STAMP 260 C" at 413.03,200.277 h2.39
  text "20. ALL PLATED AND NON-PLATED THROUGH HOLES ARE TO BE DRILLED AT PRIMARY DRILL STEP." at 430.749,191.666 h2.39
  text "ALL HOLE LOCATION TOLERANCES ARE TO BE +/-.002 IN REFERENCE TO THE PRIMARY DATUM." at 439.71,186.967 h2.39
  text "21. FINISHED PCB MUST BE PANELIZED FOR ASSEMBLY ACCORDING TO CONTRACT MANUFACTURING REQUIREMENT." at 413.563,178.712 h2.39
  text "ADDITION OF .25\" RAILS AND .125\" NON-PLATED TOOLING HOLES ARE AT THE DISCRETION" at 422.453,174.14 h2.39
  text "OF CONTRACT MANUFACTURER AND FAB HOUSE." at 422.453,169.822 h2.39
  text "PANELIZATION MUST BE APPROVED BY FREESCALE." at 422.453,164.742 h2.39
  text "NO-*****" at 556.756,26.59 h3.17
  text "THIS DOCUMENT CONTAINS INFORMATION" at 551.485,20.79 h1.6
  text "___ PUBI (PUBLIC INFORMATION)" at 479.222,19.901 h1.6
  text "HYOC" at 616.509,17.996 h5.71
  text "PROPRIETARY TO FREESCALE AND SHALL" at 551.485,17.615 h1.6
  text "NOT BE USED FOR ENGINEERING DESIGN" at 551.485,14.44 h1.6
  text "___ FIUO (HY INTERNAL USE ONLY)" at 479.222,12.281 h1.6
  text "X" at 480.238,12.281 h2.54
  text "PROCUREMENT OR MANUFACTURE IN WHOLE" at 551.485,11.265 h1.6
  text "OR IN PART WITHOUT THE CONSENT OF" at 551.485,8.09 h1.6
  text "NXP." at 551.485,4.915 h1.6
  text "___ FCP (HY CONFIDENTIAL PROPRIETARY)" at 479.222,4.661 h1.6
  text "XXXLZJXXX" at 561.264,-11.341 h2.54
  text "DRV8711_TEST_V10A" at 653.085,-15.532 h4.44
  text "XXXLZJXXX" at 561.137,-22.009 h2.54
  text "XXXLZJXXX" at 561.01,-32.042 h2.54
  text "19_02_15" at 593.332,-32.042 h2.54
  text "CAD-*****" at 625.907,-32.55 h3.17
  text "FAB-*****" at 679.374,-32.55 h4.44
  text "A2" at 739.826,-32.55 h4.44
  text "1/1" at 625.005,-42.625 h3.17
  text "1" at 734.962,-42.647 h3.17
  text "1" at 721.881,-42.774 h3.17
DRAWING_ORIGIN:
  lines w0.025: -0.635,0 0.635,0 ; 0,-0.635 0,0.635
PANEL:
  lines w0.025: -7.874,0 -0.207,0 ; -0.207,0 -4.017,0.635 -4.017,-0.635 -0.207,0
